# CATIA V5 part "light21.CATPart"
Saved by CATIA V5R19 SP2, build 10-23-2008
Part number: light21
Bounding box of the stored display mesh (mm): x -1260.893 to -486.867, y -621.662 to 621.662, z 560.173 to 628.346
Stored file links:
  C:\BEHROOZ\catia learning\tarh haye mashin\hb\light21.CATPart
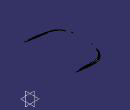
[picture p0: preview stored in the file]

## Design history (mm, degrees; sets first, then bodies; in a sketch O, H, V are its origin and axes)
Body1 (main body)
  DatumSurface1
  ThickSurface1: Surface DatumSurface1, TopOffset 0.5, BotOffset -1
  DatumSurface2
  Plane1: stored without definition
  ThickSurface2: Surface DatumSurface2, TopOffset 0.5, BotOffset -1
  Sketch1 on Plane1, origin (-400.5776, -753.3763, 758.3765), H (0.8829, -0.4695, 0), V (0.3119, 0.5866, 0.7474)
    arc A1 centre (-612.4323, 244.0436) radius 490.3943 from (-984.8074, -75.0542) to (-785.3772, -214.8427) ccw
    arc A2 centre (-692.8271, 256.1098) radius 488.9741 from (-679.0471, -232.6702) to (-500.789, -193.5758) ccw
    line L1 (-500.789, -193.5758) -> (-143.1164, -44.6342)
    arc A3 centre (-686.9152, 46.4132) radius 279.1942 from (-679.0471, -232.6702) to (-785.3772, -214.8427) cw
  Pocket1: profile Sketch1, direction (0.3509, 0.6599, -0.6643), length 136, opposite side length 56, thin wall 6, second thickness 6
  Mirror1: of Pocket1, about zx-plane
